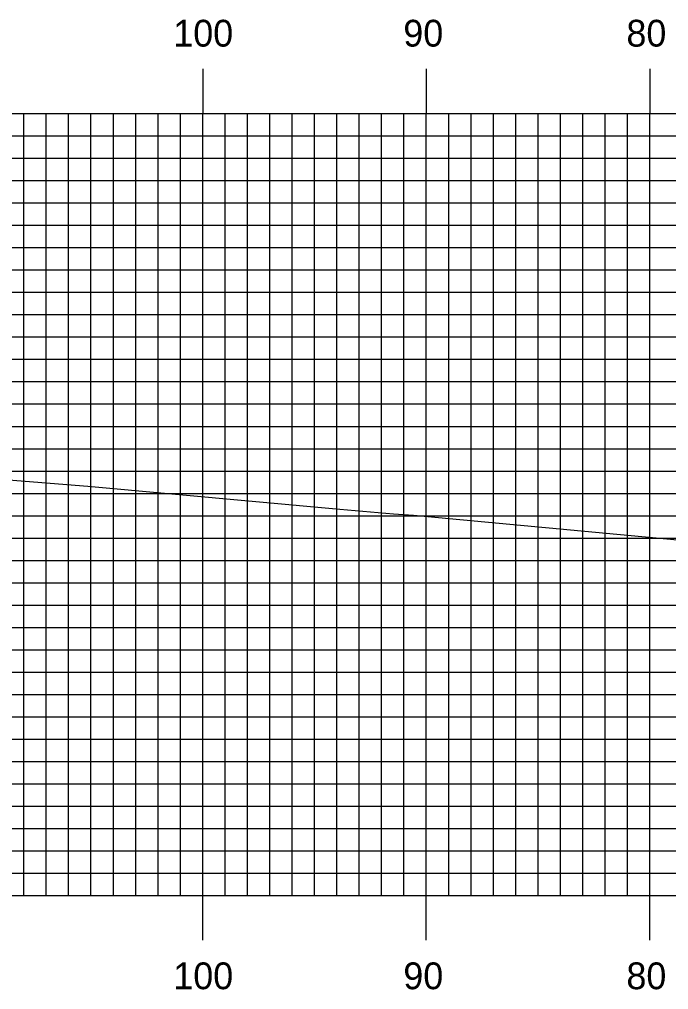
# Model space of a CAD drawing. Extents: x 1815702 to 1816046, y 442591 to 442811.
# Drawn here: x 1815759.85 to 1815788.88, y 442654.45 to 442697.88 of the extents above; entities that cross this region are included whole.
import ezdxf

# ---------------------------------------------------------------- set-up
doc = ezdxf.new("R2010")
doc.units = 0
for name, color, linetype in [('H_V ANNOTATION', 7, 'Continuous'), ('MAJOR', 7, 'Continuous'), ('MINOR', 7, 'Continuous'), ('S_Roadway_Centerline', 7, 'Continuous')]:
    doc.layers.add(name, color=color, linetype=linetype)

msp = doc.modelspace()

# ---------------------------------------------------------------- linework, layer by layer
at = {"layer": 'MAJOR'}
for p, q in [((1815768.047, 442695.669), (1815768.047, 442693.665)), ((1815778.047, 442695.669), (1815778.047, 442693.665)), ((1815788.047, 442695.669), (1815788.047, 442693.665)), ((1815728.047, 442693.665), (1816008.047, 442693.665)), ((1815728.047, 442693.665), (1816008.047, 442693.665)), ((1815768.047, 442658.665), (1815768.047, 442693.665)), ((1815778.047, 442658.665), (1815778.047, 442693.665)), ((1815788.047, 442658.665), (1815788.047, 442693.665)), ((1815728.047, 442688.665), (1816008.047, 442688.665)), ((1815728.047, 442683.665), (1816008.047, 442683.665)), ((1815728.047, 442678.665), (1816008.047, 442678.665)), ((1815728.047, 442673.665), (1816008.047, 442673.665)), ((1815728.047, 442668.665), (1816008.047, 442668.665)), ((1815728.047, 442663.665), (1816008.047, 442663.665)), ((1815728.047, 442658.665), (1816008.047, 442658.665)), ((1815728.047, 442658.665), (1816008.047, 442658.665)), ((1815768.047, 442656.661), (1815768.047, 442658.665)), ((1815778.047, 442656.661), (1815778.047, 442658.665)), ((1815788.047, 442656.661), (1815788.047, 442658.665))]:
    msp.add_line(p, q, dxfattribs=at)
at = {"layer": 'MINOR'}
for p, q in [((1815760.047, 442658.665), (1815760.047, 442693.665)), ((1815761.047, 442658.665), (1815761.047, 442693.665)), ((1815762.047, 442658.665), (1815762.047, 442693.665)), ((1815763.047, 442658.665), (1815763.047, 442693.665)), ((1815764.047, 442658.665), (1815764.047, 442693.665)), ((1815765.047, 442658.665), (1815765.047, 442693.665)), ((1815766.047, 442658.665), (1815766.047, 442693.665)), ((1815767.047, 442658.665), (1815767.047, 442693.665)), ((1815769.047, 442658.665), (1815769.047, 442693.665)), ((1815770.047, 442658.665), (1815770.047, 442693.665)), ((1815771.047, 442658.665), (1815771.047, 442693.665)), ((1815772.047, 442658.665), (1815772.047, 442693.665)), ((1815773.047, 442658.665), (1815773.047, 442693.665)), ((1815774.047, 442658.665), (1815774.047, 442693.665)), ((1815775.047, 442658.665), (1815775.047, 442693.665)), ((1815776.047, 442658.665), (1815776.047, 442693.665)), ((1815777.047, 442658.665), (1815777.047, 442693.665)), ((1815779.047, 442658.665), (1815779.047, 442693.665)), ((1815780.047, 442658.665), (1815780.047, 442693.665)), ((1815781.047, 442658.665), (1815781.047, 442693.665)), ((1815782.047, 442658.665), (1815782.047, 442693.665)), ((1815783.047, 442658.665), (1815783.047, 442693.665)), ((1815784.047, 442658.665), (1815784.047, 442693.665)), ((1815785.047, 442658.665), (1815785.047, 442693.665)), ((1815786.047, 442658.665), (1815786.047, 442693.665)), ((1815787.047, 442658.665), (1815787.047, 442693.665)), ((1815728.047, 442692.665), (1816008.047, 442692.665)), ((1815728.047, 442691.665), (1816008.047, 442691.665)), ((1815728.047, 442690.665), (1816008.047, 442690.665)), ((1815728.047, 442689.665), (1816008.047, 442689.665)), ((1815728.047, 442687.665), (1816008.047, 442687.665)), ((1815728.047, 442686.665), (1816008.047, 442686.665)), ((1815728.047, 442685.665), (1816008.047, 442685.665)), ((1815728.047, 442684.665), (1816008.047, 442684.665)), ((1815728.047, 442682.665), (1816008.047, 442682.665)), ((1815728.047, 442681.665), (1816008.047, 442681.665)), ((1815728.047, 442680.665), (1816008.047, 442680.665)), ((1815728.047, 442679.665), (1816008.047, 442679.665)), ((1815728.047, 442677.665), (1816008.047, 442677.665)), ((1815728.047, 442676.665), (1816008.047, 442676.665)), ((1815728.047, 442675.665), (1816008.047, 442675.665)), ((1815728.047, 442674.665), (1816008.047, 442674.665)), ((1815728.047, 442672.665), (1816008.047, 442672.665)), ((1815728.047, 442671.665), (1816008.047, 442671.665)), ((1815728.047, 442670.665), (1816008.047, 442670.665)), ((1815728.047, 442669.665), (1816008.047, 442669.665)), ((1815728.047, 442667.665), (1816008.047, 442667.665)), ((1815728.047, 442666.665), (1816008.047, 442666.665)), ((1815728.047, 442665.665), (1816008.047, 442665.665)), ((1815728.047, 442664.665), (1816008.047, 442664.665)), ((1815728.047, 442662.665), (1816008.047, 442662.665)), ((1815728.047, 442661.665), (1816008.047, 442661.665)), ((1815728.047, 442660.665), (1816008.047, 442660.665)), ((1815728.047, 442659.665), (1816008.047, 442659.665))]:
    msp.add_line(p, q, dxfattribs=at)
at = {"layer": 'S_Roadway_Centerline'}
msp.add_lwpolyline([(1815728.047, 442679.907), (1815735.762, 442679.888), (1815742.096, 442679.088), (1815749.087, 442678.276), (1815759.364, 442677.265), (1815762.899, 442676.985), (1815774.185, 442675.958), (1815776.581, 442675.75), (1815777.476, 442675.695), (1815792.637, 442674.271), (1815802.889, 442673.25), (1815809.563, 442672.51), (1815823.05, 442671.649)], dxfattribs=at)

# ---------------------------------------------------------------- texts
at = {"layer": 'H_V ANNOTATION'}
for s, p in [('100', (1815766.73, 442696.665)), ('90', (1815777.019, 442696.665)), ('80', (1815786.998, 442696.665)), ('100', (1815766.73, 442654.465)), ('90', (1815777.019, 442654.465)), ('80', (1815786.998, 442654.465))]:
    msp.add_text(s, height=1.2, dxfattribs=at).set_placement(p)

doc.saveas('drawing.dxf')
